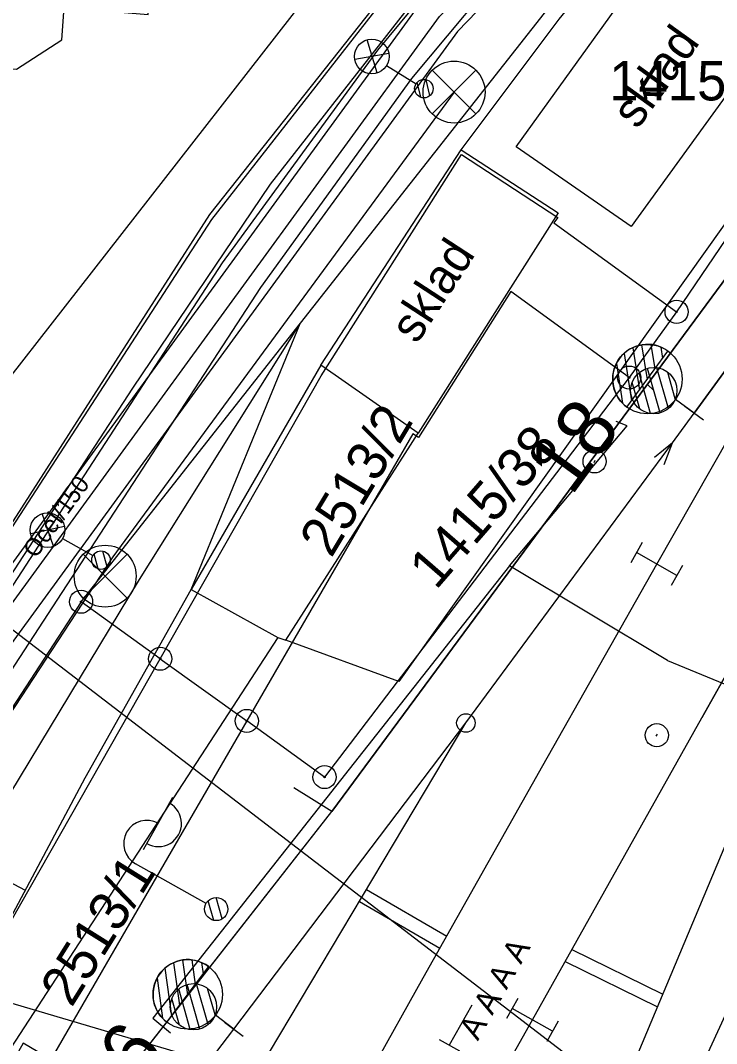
# Model space of a CAD drawing. Extents: x -781083 to -763634, y -1029516 to -1022695.
# Drawn here: x -764981.39 to -764951.32, y -1023829.68 to -1023785.5 of the extents above; entities that cross this region are included whole.
import ezdxf

# ---------------------------------------------------------------- set-up
doc = ezdxf.new("R2010")
doc.units = 0
for name, color, linetype in [('Default', 7, 'Continuous'), ('GasNet_ochr. pásmo', 7, 'Continuous'), ('GasNet_plyn STL', 7, 'Continuous'), ('Hranice parcel', 7, 'Continuous'), ('Parcelní čísla', 7, 'Continuous'), ('PS_12-01-10_Kabelizace_nove_kabelizace', 7, 'Continuous'), ('PS_12-01-11_SZZ_Slany_nove_prvky', 7, 'Continuous'), ('PS_12-01-11_SZZ_Slany_rusene_prvky', 7, 'Continuous'), ('SO128401_EOV_trasa', 7, 'Continuous'), ('TS_veřejné vedení', 7, 'Continuous'), ('Vodafone_ vzduch', 7, 'Continuous'), ('Vrstva 1', 7, 'Continuous'), ('Vrstva 17', 7, 'Continuous'), ('Vrstva 2', 7, 'Continuous'), ('Vrstva 23', 7, 'Continuous'), ('Vrstva 25', 7, 'Continuous'), ('Vrstva 28', 7, 'Continuous'), ('Vrstva 3', 7, 'Continuous'), ('Vrstva 33', 7, 'Continuous'), ('Vrstva 48', 7, 'Continuous'), ('Vrstva 49', 7, 'Continuous'), ('Vrstva 50', 7, 'Continuous'), ('Vrstva 51', 7, 'Continuous'), ('Vrstva 7', 7, 'Continuous'), ('Značky bodu BP', 7, 'Continuous'), ('ČD Telematika_TK', 7, 'Continuous'), ('ČEZd_VN_podzemní', 7, 'Continuous')]:
    doc.layers.add(name, color=color, linetype=linetype)

# ---------------------------------------------------------------- blocks, each defined once
blk = doc.blocks.new('TS osvětlení')
at = {"layer": 'TS_veřejné vedení'}
blk.add_line((-7649635.99, -10237876.43), (-7649617.09, -10237895.34), dxfattribs=at)
blk.add_lwpolyline([(-7649635.99, -10237895.34), (-7649617.09, -10237876.43)], dxfattribs=at)
blk.add_circle((-7649626.54, -10237885.89), 13.37, dxfattribs=at)
blk = doc.blocks.new('1.05')
at = {"layer": 'Značky bodu BP'}
for radius in [5, 0.303]:
    blk.add_circle((0, 0), radius, dxfattribs=at)
blk = doc.blocks.new('C669_5')
at = {"layer": 'Vrstva 25'}
for p, q in [((0.01, 5), (0, 40.01)), ((6.99, 40), (33, 40.01)), ((-4.78, -1.46), (1.43, 4.76)), ((-2.39, -4.37), (4.37, 2.4))]:
    blk.add_line(p, q, dxfattribs=at)
blk.add_circle((0, 0), 5, dxfattribs=at)
blk.add_circle((0, 0), 5, dxfattribs=at)
for centre, start, end in [((10, 40), 359.9998, 179.9998), ((20, 39.88), 179.2972, 0.7024)]:
    blk.add_arc(centre, 10, start, end, dxfattribs=at)
blk = doc.blocks.new('C187_5')
at = {"layer": 'Vrstva 25'}
for p, q in [((-4.94, 32.07), (5, 20.95)), ((-4.79, 20.76), (5.05, 31.98)), ((0, 19), (0, 4)), ((-3.89, -0.8), (0.81, 3.89)), ((-1.21, -3.77), (3.79, 1.23))]:
    blk.add_line(p, q, dxfattribs=at)
for centre, radius in [((-0.03, 26.49), 7.49), ((0, 0), 4), ((0, 0), 4)]:
    blk.add_circle(centre, radius, dxfattribs=at)
blk = doc.blocks.new('C187_7')
at = {"layer": 'Vrstva 25'}
for p, q in [((-4.94, 32.07), (5, 20.95)), ((-4.78, 20.77), (5.05, 31.98)), ((0, 19), (0.01, 4)), ((-3.89, -0.8), (0.8, 3.89)), ((-1.21, -3.77), (3.79, 1.23))]:
    blk.add_line(p, q, dxfattribs=at)
for centre, radius in [((-0.03, 26.48), 7.49), ((0, 0), 4), ((0, 0), 4)]:
    blk.add_circle(centre, radius, dxfattribs=at)
blk = doc.blocks.new('C053_1')
at = {"layer": 'Vrstva 25'}
blk.add_line((-0.51, 0), (0.51, 0), dxfattribs=at)
blk.add_circle((0, 0), 5, dxfattribs=at)
blk = doc.blocks.new('C053_5')
at = {"layer": 'Vrstva 50'}
blk.add_line((-0.51, 0), (0.51, 0), dxfattribs=at)
blk.add_circle((0, 0), 5, dxfattribs=at)
blk = doc.blocks.new('C649_1')
at = {"layer": 'Vrstva 3'}
for p, q in [((-5, 10), (5, 10)), ((0, 10), (0, -10)), ((-5, -10), (5, -10))]:
    blk.add_line(p, q, dxfattribs=at)
blk = doc.blocks.new('C321')
at = {"layer": 'Vrstva 2'}
blk.add_lwpolyline([(9.66, 2.59), (0, 0), (9.66, -2.59)], dxfattribs=at)
blk = doc.blocks.new('C083_1')
at = {"layer": 'Vrstva 2'}
blk.add_circle((0, 0), 4, dxfattribs=at)
blk = doc.blocks.new('C529')
at = {"layer": 'Vrstva 2'}
for p, q in [((-2.45, 39.78), (-14.76, 27.47)), ((3.07, 39.65), (-11.57, 25)), ((7.2, 38.12), (-5.92, 25)), ((10.45, 35.71), (-0.26, 25)), ((12.93, 32.53), (5.4, 25)), ((14.55, 28.49), (11.05, 25)), ((0, 0), (0, 10))]:
    blk.add_line(p, q, dxfattribs=at)
blk.add_lwpolyline([(-15, 25), (15, 25)], dxfattribs=at)
blk.add_circle((0, 25), 15, dxfattribs=at)
blk.add_arc((0, 25), 15, 0, 180, dxfattribs=at)
blk = doc.blocks.new('C529_1')
at = {"layer": 'Vrstva 2'}
for p, q in [((-2.45, 39.78), (-14.76, 27.47)), ((3.07, 39.65), (-11.57, 25)), ((7.2, 38.12), (-5.92, 25)), ((10.45, 35.71), (-0.26, 25)), ((12.93, 32.53), (5.4, 25)), ((14.55, 28.49), (11.05, 25)), ((0, 0), (0, 10))]:
    blk.add_line(p, q, dxfattribs=at)
blk.add_lwpolyline([(-15, 25), (15, 25)], dxfattribs=at)
blk.add_circle((0, 25), 15, dxfattribs=at)
blk.add_arc((0, 25), 15, 0, 180, dxfattribs=at)
blk = doc.blocks.new('C084_2')
at = {"layer": 'Vrstva 2'}
blk.add_line((0, 5), (0, -5), dxfattribs=at)
blk = doc.blocks.new('POINT_DISPLAY')
at = {"layer": 'Default'}
blk.add_line((0, 0), (0, 0), dxfattribs=at)
blk = doc.blocks.new('C335')
at = {"layer": 'Vrstva 7'}
blk.add_blockref('POINT_DISPLAY', (0, 0), dxfattribs=at)
blk = doc.blocks.new('C016_4')
at = {"layer": 'PS_12-01-11_SZZ_Slany_rusene_prvky'}
for p, q in [((0, 5), (0, -5)), ((19.8, 0), (0, 0))]:
    blk.add_line(p, q, dxfattribs=at)
blk = doc.blocks.new('C649_1_1')
at = {"layer": 'PS_12-01-11_SZZ_Slany_rusene_prvky'}
for p, q in [((-5, 10), (5, 10)), ((0, 10), (0, -10)), ((-5, -10), (5, -10))]:
    blk.add_line(p, q, dxfattribs=at)
blk = doc.blocks.new('PZ2_2')
at = {"layer": 'PS_12-01-11_SZZ_Slany_nove_prvky'}
for p, q in [((-14.74, 0.11), (-20.2, 19.3)), ((-11.12, 2.04), (-16.13, 19.62)), ((-18.83, -0.14), (-23.82, 17.41)), ((-8.14, 6.18), (-11.41, 17.64)), ((-23.54, 1.82), (-26.79, 13.24))]:
    blk.add_line(p, q, dxfattribs=at)
blk.add_circle((-17.47, 9.73), 10, dxfattribs=at)

msp = doc.modelspace()

# ---------------------------------------------------------------- linework, layer by layer
at = {"layer": 'GasNet_ochr. pásmo'}
for points in [[(-765004.735, -1023844.204), (-764987.098, -1023816.295), (-764964.047, -1023784.681), (-764954.572, -1023774.882), (-764954.336, -1023774.638), (-764953.664, -1023774.538), (-764953.368, -1023774.703), (-764949.815, -1023776.676), (-764944.807, -1023779.62), (-764944.555, -1023779.767), (-764928.407, -1023789.665)], [(-764926.927, -1023792.918), (-764945.583, -1023781.483), (-764945.819, -1023781.344), (-764950.807, -1023778.412), (-764953.668, -1023776.824), (-764962.513, -1023785.971), (-764985.442, -1023817.419), (-765003.137, -1023845.42), (-765021.725, -1023865.911)]]:
    msp.add_lwpolyline(points, dxfattribs=at)
at = {"layer": 'GasNet_plyn STL'}
msp.add_lwpolyline([(-765056.262, -1023868.365), (-765056.064, -1023868.32), (-765055.22, -1023868.128), (-765047.384, -1023866.918), (-765047.344, -1023866.915), (-765022.199, -1023864.945), (-765003.936, -1023844.812), (-764986.27, -1023816.857), (-764963.28, -1023785.326), (-764953.853, -1023775.577), (-764950.311, -1023777.544), (-764945.313, -1023780.482), (-764945.069, -1023780.625), (-764927.667, -1023791.291)], dxfattribs=at)
at = {"layer": 'Hranice parcel'}
for p, q in [((-764953.04, -1023798.08), (-764955.09, -1023800.92)), ((-764975.35, -1023813.06), (-764978.77, -1023810.6)), ((-764975.35, -1023813.06), (-764971.61, -1023815.75))]:
    msp.add_line(p, q, dxfattribs=at)
for points in [[(-764992.56, -1023786.82), (-764981.56, -1023787.6), (-764979.6, -1023786.33), (-764979.5, -1023784.94), (-764975.87, -1023785.24), (-764975.41, -1023778.43), (-764975, -1023772.47)], [(-764986.64, -1023807.05), (-764984.91, -1023804.83), (-764969.09, -1023784.55), (-764969.6, -1023772.89)], [(-764969.6, -1023772.89), (-764957.34, -1023773.9), (-764973.13, -1023794.09), (-764983.68, -1023810.31)], [(-764978.77, -1023810.6), (-764955.77, -1023781.38), (-764950.74, -1023775.95), (-764945.55, -1023773.21), (-764940.98, -1023772.86)], [(-764940.98, -1023772.86), (-764939.38, -1023777.94), (-764953.04, -1023798.08)], [(-764975.35, -1023813.06), (-764968.39, -1023800.84), (-764962.33, -1023791.29), (-764958.18, -1023794), (-764958.35, -1023794.23), (-764953.04, -1023798.08)], [(-764955.09, -1023800.92), (-764960.21, -1023797.2), (-764964.19, -1023803.5), (-764964.43, -1023803.35), (-764971.61, -1023815.75)], [(-764955.09, -1023800.92), (-764968.25, -1023818.17), (-764971.61, -1023815.75)], [(-764978.77, -1023810.6), (-765003.52, -1023848.6), (-765036.72, -1023885.86)], [(-764971.61, -1023815.75), (-764975.67, -1023822.76), (-764980.08, -1023830.37), (-764981.27, -1023829.66), (-764988.11, -1023841.84), (-764987.77, -1023842.03), (-764990.21, -1023846.47), (-764993.84, -1023844.39), (-764991.38, -1023840.01), (-764990.86, -1023840.3), (-764975.35, -1023813.06)]]:
    msp.add_lwpolyline(points, dxfattribs=at)
at = {"layer": 'PS_12-01-10_Kabelizace_nove_kabelizace'}
for p, q in [((-764954.03, -1023801.484), (-764954.309, -1023801.206)), ((-765005.156, -1023867.179), (-764967.937, -1023819.655))]:
    msp.add_line(p, q, dxfattribs=at)
msp.add_lwpolyline([(-764942.036, -1023784.592), (-764967.937, -1023819.655), (-764969.577, -1023818.635)], dxfattribs=at)
at = {"layer": 'SO128401_EOV_trasa'}
msp.add_lwpolyline([(-764973.93, -1023884.565), (-765005.156, -1023867.179), (-764967.937, -1023819.655), (-764942.036, -1023784.592), (-764937.448, -1023776.793), (-764936.433, -1023777.403)], dxfattribs=at)
at = {"layer": 'TS_veřejné vedení'}
msp.add_lwpolyline([(-764962.654, -1023788.589), (-764977.401, -1023808.657), (-764993.006, -1023832.465), (-765002.622, -1023846.533)], dxfattribs=at)
at = {"layer": 'Vodafone_ vzduch'}
msp.add_line((-764902.64, -1023851.29), (-765047.77, -1023808.471), dxfattribs=at)
at = {"layer": 'Vrstva 1'}
for points in [[(-765011.125, -1023882.032), (-765006.787, -1023874.584), (-765003.188, -1023868.775), (-765000.244, -1023864.367), (-764995.829, -1023858.264), (-764991.795, -1023853.119), (-764989.992, -1023850.92), (-764988.125, -1023848.704), (-764979.186, -1023837.995), (-764972.943, -1023830.075), (-764972.169, -1023829.066), (-764962.145, -1023815.837), (-764953.22, -1023803.742), (-764952.283, -1023802.457), (-764942.467, -1023789.001), (-764933.609, -1023776.857), (-764932.714, -1023775.624), (-764932.358, -1023775.126), (-764928.839, -1023770.209), (-764926.844, -1023767.42), (-764917.098, -1023753.973), (-764910.61, -1023742.572)], [(-765057.199, -1024002.967), (-765051.483, -1023992.806), (-765043.706, -1023978.953), (-765034.751, -1023962.958), (-765025.899, -1023947.163), (-765016.568, -1023930.575), (-765007.818, -1023915.05), (-764998.815, -1023899.045), (-764993.349, -1023889.308), (-764987.511, -1023878.918), (-764981.006, -1023867.343), (-764973.154, -1023853.353), (-764966.496, -1023841.495), (-764959.274, -1023828.66), (-764951.948, -1023815.612), (-764946.772, -1023806.407), (-764938.618, -1023791.934), (-764931.244, -1023778.835), (-764930.485, -1023777.473), (-764927.033, -1023771.438), (-764925.317, -1023768.417), (-764917.098, -1023753.973)], [(-765061.157, -1024000.548), (-765054.406, -1023988.525), (-765046.25, -1023974.042), (-765038.306, -1023959.907), (-765029.522, -1023944.29), (-765019.951, -1023927.223), (-765010.85, -1023911.039), (-765002.788, -1023896.651), (-764999.751, -1023891.219), (-764995.793, -1023884.104), (-764991.163, -1023875.777), (-764986.062, -1023866.575), (-764981.011, -1023857.454), (-764976.168, -1023848.713), (-764971.336, -1023840.024), (-764966.193, -1023830.79), (-764963.989, -1023826.843), (-764958.821, -1023817.674), (-764953.901, -1023808.973), (-764950.727, -1023803.418), (-764942.467, -1023789.001)], [(-765021.966, -1023959.899), (-765020.98, -1023958.139), (-765020.338, -1023956.998), (-765016.5, -1023950.137), (-765007.832, -1023934.643), (-765003.16, -1023926.347), (-764995.027, -1023911.884), (-764988.083, -1023899.535), (-764983.024, -1023890.503), (-764978.046, -1023881.533), (-764973.443, -1023872.721), (-764971.379, -1023868.593), (-764967.7, -1023860.663), (-764964.253, -1023852.828), (-764961.628, -1023846.609), (-764955.193, -1023831.268), (-764949.378, -1023817.406), (-764948.769, -1023815.942), (-764946.974, -1023811.649), (-764945.113, -1023807.171), (-764938.618, -1023791.934)], [(-765066.823, -1024000.8), (-765059.521, -1023987.798), (-765051.083, -1023972.749), (-765042.307, -1023957.114), (-765034.527, -1023943.229), (-765024.842, -1023926.012), (-765014.604, -1023907.749), (-765007.197, -1023894.564), (-765001.299, -1023884.061), (-764995.865, -1023874.378), (-764990.286, -1023864.419), (-764985.503, -1023855.894), (-764983.132, -1023851.684), (-764978.128, -1023842.798), (-764973.494, -1023834.781), (-764970.63, -1023830.052), (-764962.145, -1023815.837)]]:
    msp.add_lwpolyline(points, dxfattribs=at)
at = {"layer": 'Vrstva 17'}
for points in [[(-764967.173, -1023772.995), (-764957.403, -1023773.908), (-764973.218, -1023793.881)], [(-764947.614, -1023774.034), (-764947.19, -1023773.732), (-764940.917, -1023774.757), (-764939.323, -1023777.947), (-764965.037, -1023814.04)], [(-764962.354, -1023791.081), (-764958.112, -1023785.44), (-764955.981, -1023782.82), (-764953.732, -1023780.351), (-764950.895, -1023777.549)], [(-764973.218, -1023793.881), (-764985.425, -1023812.874), (-764997.633, -1023831.896), (-765001.548, -1023838.038), (-765015.627, -1023854.487), (-765019.894, -1023858.999)], [(-764970.268, -1023812.149), (-764984.37, -1023833.783)], [(-764965.037, -1023814.04), (-764969.92, -1023812.263)]]:
    msp.add_lwpolyline(points, dxfattribs=at)
at = {"layer": 'Vrstva 2'}
msp.add_line((-764970.63, -1023830.052), (-764962.145, -1023815.837), dxfattribs=at)
for points in [[(-764932.714, -1023775.624), (-764933.609, -1023776.857), (-764942.467, -1023789.001), (-764952.283, -1023802.457)], [(-764930.485, -1023777.473), (-764931.244, -1023778.835), (-764938.618, -1023791.934), (-764946.772, -1023806.407), (-764951.948, -1023815.612)], [(-764972.169, -1023829.066), (-764962.145, -1023815.837), (-764953.22, -1023803.742), (-764952.283, -1023802.457)], [(-764961.628, -1023846.609), (-764955.193, -1023831.268), (-764949.378, -1023817.406), (-764948.769, -1023815.942)], [(-764988.125, -1023848.704), (-764979.186, -1023837.995), (-764972.943, -1023830.075), (-764972.169, -1023829.066)]]:
    msp.add_lwpolyline(points, dxfattribs=at)
at = {"layer": 'Vrstva 23'}
for points in [[(-764955, -1023794.4), (-764959.98, -1023790.954), (-764951.178, -1023778.731), (-764946.17, -1023782.181), (-764955, -1023794.4)], [(-764962.354, -1023791.081), (-764958.159, -1023793.799), (-764964.206, -1023803.316), (-764968.414, -1023800.379), (-764962.354, -1023791.081)], [(-764968.414, -1023800.379), (-764974.02, -1023810.068), (-764970.268, -1023812.149), (-764969.92, -1023812.263), (-764964.206, -1023803.316)]]:
    msp.add_lwpolyline(points, dxfattribs=at)
at = {"layer": 'Vrstva 28'}
for points in [[(-764953.431, -1023813.145), (-764944.937, -1023816.641), (-764934.585, -1023793.979), (-764945.041, -1023787.992)], [(-764960.257, -1023809.048), (-764955.184, -1023802.997)], [(-764955.184, -1023802.997), (-764955.658, -1023802.82)], [(-764953.431, -1023813.145), (-764960.257, -1023809.048), (-764975.673, -1023828.591), (-764974.904, -1023829.224)]]:
    msp.add_lwpolyline(points, dxfattribs=at)
at = {"layer": 'Vrstva 33'}
msp.add_lwpolyline([(-764999.728, -1023799.281), (-764994.59, -1023801.95), (-764951.393, -1023835.06)], dxfattribs=at)
at = {"layer": 'Vrstva 48'}
msp.add_line((-764983.589, -1023821.778), (-764981.185, -1023823.06), dxfattribs=at)
at = {"layer": 'Vrstva 49'}
for points in [[(-765026.593, -1023885.365), (-764999.705, -1023850.781), (-764986.63, -1023833.272), (-764978.594, -1023818.199), (-764974.02, -1023810.068), (-764969.31, -1023798.584)], [(-764976.248, -1023809.635), (-764969.31, -1023798.584)], [(-765029.569, -1023877.256), (-765024.382, -1023871.68), (-765019.041, -1023864.807), (-765012, -1023857.823), (-764995.786, -1023840.409), (-764991.309, -1023834.549), (-764976.248, -1023809.635)]]:
    msp.add_lwpolyline(points, dxfattribs=at)
at = {"layer": 'Vrstva 51'}
for points in [[(-764965.956, -1023786.782), (-764957.275, -1023776.311), (-764955.814, -1023773.93)], [(-764964.48, -1023788.003), (-764955.24, -1023776.938), (-764953.637, -1023774.372), (-764949.357, -1023776.288)], [(-764996.351, -1023832.643), (-764984.218, -1023813.742), (-764972.656, -1023795.959), (-764965.956, -1023786.782)], [(-764994.686, -1023833.618), (-764982.455, -1023814.573), (-764971.01, -1023797.036), (-764964.48, -1023788.003)]]:
    msp.add_lwpolyline(points, dxfattribs=at)
at = {"layer": 'Vrstva 7'}
for p, q in [((-764966.437, -1023823.027), (-764962.971, -1023825.038)), ((-764966.744, -1023823.542), (-764963.266, -1023825.56)), ((-764957.567, -1023825.62), (-764953.63, -1023827.543)), ((-764957.861, -1023826.144), (-764953.863, -1023828.097))]:
    msp.add_line(p, q, dxfattribs=at)
at = {"layer": 'ČD Telematika_TK'}
msp.add_lwpolyline([(-764972.556, -1023882.882), (-764969.78, -1023867.575), (-764954.962, -1023837.207), (-764946.646, -1023819.145), (-764922.208, -1023770.145), (-764907.866, -1023743.998)], dxfattribs=at)
at = {"layer": 'ČEZd_VN_podzemní'}
msp.add_lwpolyline([(-764917.991, -1023810.215), (-764918.562, -1023807.51), (-764919.66, -1023802.13), (-764920.94, -1023798.44), (-764932.4, -1023789.85), (-764941.94, -1023783.52), (-764953.83, -1023776.39), (-764957.16, -1023777.16), (-764959.07, -1023778.2), (-764961.32, -1023780.7), (-764970.6, -1023792.56), (-764976.55, -1023801.37), (-764982.69, -1023810.79), (-764988.88, -1023820.11), (-764995.81, -1023830.85), (-765001.33, -1023839.24), (-765010.71, -1023850.19)], dxfattribs=at)

# ---------------------------------------------------------------- block references
at = {"layer": 'PS_12-01-11_SZZ_Slany_nove_prvky', "xscale": 0.1, "yscale": 0.10000000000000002}
for p in [(-764952.283, -1023802.457), (-764972.169, -1023829.066)]:
    msp.add_blockref('PZ2_2', p, dxfattribs=at)
at = {"layer": 'PS_12-01-11_SZZ_Slany_rusene_prvky'}
for name, p, xscale, yscale, rotation in [('C649_1_1', (-764953.901, -1023808.973), 0.09999999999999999, 0.09999999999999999, -119.48608618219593), ('C016_4', (-764962.863, -1023829.751), 0.1, 0.10000000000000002, 60.65434903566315)]:
    msp.add_blockref(name, p, dxfattribs=dict(at, xscale=xscale, yscale=yscale, rotation=rotation))
at = {"layer": 'TS_veřejné vedení', "xscale": 0.1, "yscale": 0.10000000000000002}
for p in [(0, 0), (-15.075, -20.906)]:
    msp.add_blockref('TS osvětlení', p, dxfattribs=at)
at = {"layer": 'Vrstva 2'}
for name, p, xscale, yscale, rotation in [('C529', (-764952.283, -1023802.457), 0.09999999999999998, 0.09999999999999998, 53.90110957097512), ('C084_2', (-764952.283, -1023802.457), 0.10000000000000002, 0.1, -126.10899806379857), ('C321', (-764953.22, -1023803.742), 0.09999999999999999, 0.1, -126.0988904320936), ('C083_1', (-764962.145, -1023815.837), 0.10000000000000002, 0.1, -126.76682414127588), ('C529_1', (-764972.169, -1023829.066), 0.09999999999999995, 0.09999999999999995, 52.84766995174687), ('C084_2', (-764972.169, -1023829.066), 0.09999999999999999, 0.09999999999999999, 52.84767015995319)]:
    msp.add_blockref(name, p, dxfattribs=dict(at, xscale=xscale, yscale=yscale, rotation=rotation))
at = {"layer": 'Vrstva 25'}
for name, p, xscale, yscale, rotation in [('C187_5', (-764963.958, -1023788.441), 0.09999999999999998, 0.09999999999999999, 58.266139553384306), ('C053_1', (-764956.584, -1023804.537), 0.09999999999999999, 0.09999999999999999, 60.56497035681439), ('C187_7', (-764977.91, -1023808.803), 0.09999999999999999, 0.09999999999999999, 60.56497035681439), ('C669_5', (-764972.931, -1023823.873), 0.10000000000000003, 0.10000000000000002, 60.665278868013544)]:
    msp.add_blockref(name, p, dxfattribs=dict(at, xscale=xscale, yscale=yscale, rotation=rotation))
at = {"layer": 'Vrstva 3'}
for p, xscale, yscale, rotation in [((-764953.901, -1023808.973), 0.1, 0.10000000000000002, -119.48608618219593), ((-764959.274, -1023828.66), 0.09999999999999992, 0.09999999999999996, -119.36559478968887)]:
    msp.add_blockref('C649_1', p, dxfattribs=dict(at, xscale=xscale, yscale=yscale, rotation=rotation))
at = {"layer": 'Vrstva 50', "xscale": 0.09999999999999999, "yscale": 0.09999999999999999, "rotation": 60.56497035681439}
msp.add_blockref('C053_5', (-764953.897, -1023816.365), dxfattribs=at)
at = {"layer": 'Vrstva 7', "xscale": 0.10000000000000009, "yscale": 0.10000000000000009, "rotation": 90}
for p in [(-764964.796, -1023824.326), (-764955.911, -1023826.763)]:
    msp.add_blockref('C335', p, dxfattribs=at)
at = {"layer": 'Značky bodu BP', "xscale": 0.1, "yscale": 0.10000000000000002}
for p in [(-764953.04, -1023798.08), (-764955.09, -1023800.92), (-764978.77, -1023810.6), (-764975.35, -1023813.06), (-764971.61, -1023815.75), (-764968.25, -1023818.17)]:
    msp.add_blockref('1.05', p, dxfattribs=at)

# ---------------------------------------------------------------- texts
at = {"layer": 'GasNet_plyn STL'}
msp.add_text('Ocel/150', height=0.75, rotation=53.9033, dxfattribs=at).set_placement((-764980.729, -1023808.762))
at = {"layer": 'Parcelní čísla'}
msp.add_text('1415/37', height=1.7, dxfattribs=at).set_placement((-764955.95, -1023788.95))
for s, rotation, p in [('2513/2', 59, (-764967.961, -1023808.747)), ('1415/38', 49, (-764963.438, -1023810.127)), ('2513/1', 58, (-764979.179, -1023828.16))]:
    msp.add_text(s, height=1.7, rotation=rotation, dxfattribs=at).set_placement(p)
at = {"layer": 'PS_12-01-11_SZZ_Slany_rusene_prvky'}
msp.add_text('  A A A A ', height=1, rotation=60.6543, dxfattribs=at).set_placement((-764961.991, -1023830.241))
at = {"layer": 'Vrstva 2'}
for s, rotation, p in [('18', 53.9011, (-764957.594, -1023806.08)), ('16', 52.8477, (-764977.313, -1023832.982))]:
    msp.add_text(s, height=2.5, rotation=rotation, dxfattribs=at).set_placement(p)
at = {"layer": 'Vrstva 23'}
for rotation, p in [(54.2417, (-764954.735, -1023790.236)), (56.9056, (-764964.263, -1023799.509))]:
    msp.add_text('sklad', height=1.5, rotation=rotation, dxfattribs=at).set_placement(p)

doc.saveas('drawing.dxf')
